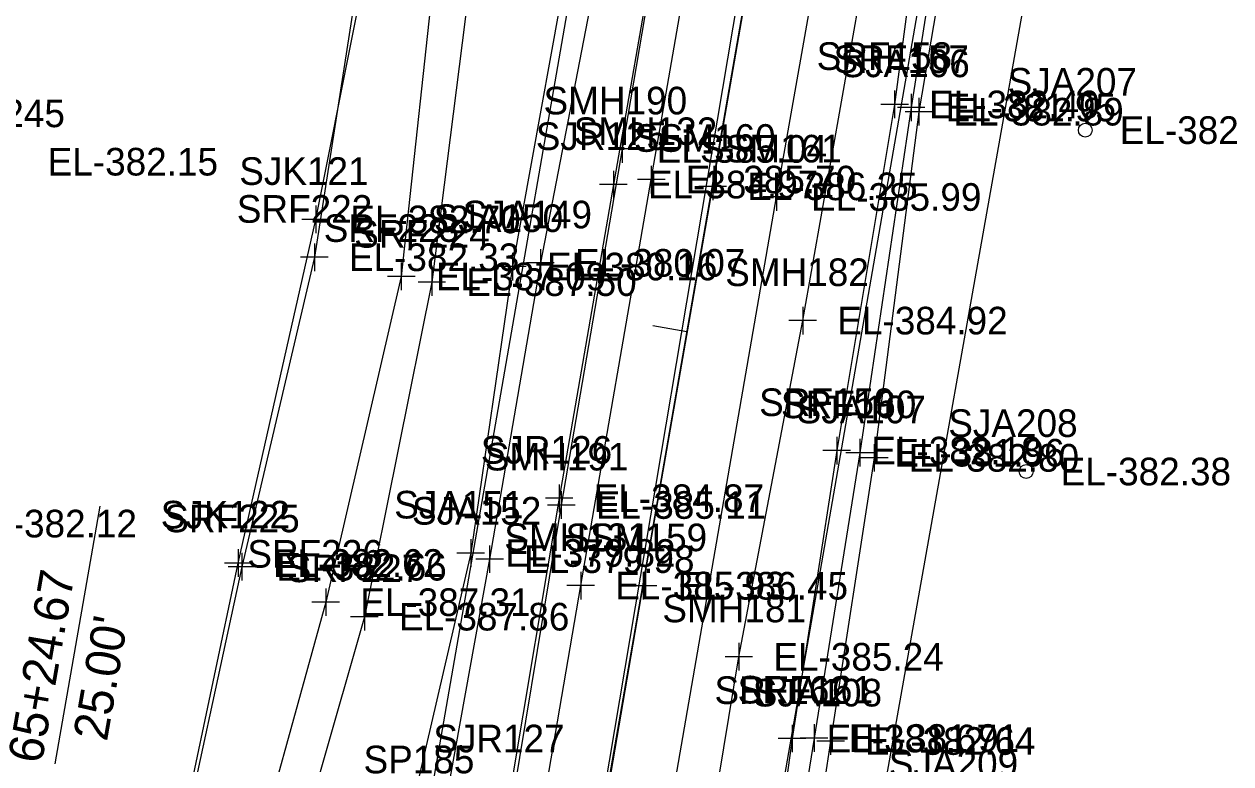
# Model space of a CAD drawing. Extents: x 1189978 to 1314812, y 571533 to 629339.
# Drawn here: x 1217588.4 to 1217763.2, y 622256.8 to 622363.9 of the extents above; entities that cross this region are included whole.
import ezdxf

# ---------------------------------------------------------------- set-up
doc = ezdxf.new("R2010")
doc.units = 0
for name, color, linetype in [('SURVEY - CENTERLINE - Preliminary', 7, 'Continuous'), ('SURVEY - CENTERLINE - Preliminary Text', 7, 'Continuous'), ('SURVEY - DRAINAGE - Area Shapes', 7, 'Continuous'), ('SURVEY - DTM - Breaklines', 7, 'Continuous'), ('SURVEY - DTM - Breaklines - Points - Elevations', 7, 'Continuous'), ('SURVEY - DTM - Breaklines - Points - Locators', 7, 'Continuous'), ('SURVEY - DTM - Breaklines - Points - Numbers', 7, 'Continuous'), ('SURVEY - DTM - Spot Points - Elevations', 7, 'Continuous'), ('SURVEY - DTM - Spot Points - Locators', 7, 'Continuous'), ('SURVEY - DTM - Spot Points - Point Numbers', 7, 'Continuous'), ('SURVEY - PROPERTY - ROW Lines', 7, 'Continuous'), ('SURVEY - PROPERTY - ROW Lines - Points - Numbers', 7, 'Continuous'), ('SURVEY - PROPERTY - Station and Offset Flags', 7, 'Continuous'), ('SURVEY - TRANSPORTATION - Roads', 7, 'Continuous'), ('SURVEY - TRANSPORTATION - Roads - Points - Elevations', 7, 'Continuous'), ('SURVEY - TRANSPORTATION - Roads - Points - Locators', 7, 'Continuous'), ('SURVEY - TRANSPORTATION - Roads - Points - Numbers', 7, 'Continuous'), ('SURVEY - UTILITIES - Electric (Overhead) with Text', 7, 'Continuous'), ('SURVEY - VEGETATION - Features - Points - Elevations', 7, 'Continuous'), ('SURVEY - VEGETATION - Features - Points - Locators', 7, 'Continuous'), ('SURVEY - VEGETATION - Features - Points - Numbers', 7, 'Continuous'), ('SURVEY - VEGETATION - Features with Text', 7, 'Continuous')]:
    doc.layers.add(name, color=color, linetype=linetype)

msp = doc.modelspace()

# ---------------------------------------------------------------- linework, layer by layer
at = {"layer": 'SURVEY - CENTERLINE - Preliminary'}
msp.add_line((1217671.49, 622245.09), (1217757.38, 622738.49), dxfattribs=at)
msp.add_line((1217671.49, 622245.09), (1217757.38, 622738.49), dxfattribs=at)
at = {"layer": 'SURVEY - CENTERLINE - Preliminary Text'}
msp.add_line((1217684.41, 622319.31), (1217679.48, 622320.17), dxfattribs=at)
at = {"layer": 'SURVEY - DRAINAGE - Area Shapes'}
msp.add_line((1217415.87, 620731.68), (1218149.36, 625079.9), dxfattribs=at)
at = {"layer": 'SURVEY - DTM - Breaklines'}
for points in [[(1217591.74, 621765.73), (1217601.34, 621822.74), (1217608.84, 621869.52), (1217625.54, 621971.19), (1217634.6, 622026.63), (1217643.17, 622076.74), (1217651.21, 622124.47), (1217659.56, 622173.57), (1217668.17, 622224.78), (1217678.08, 622282.54), (1217688.16, 622340.37), (1217697.26, 622392.62), (1217705.46, 622440.01), (1217714.49, 622490.86), (1217723.28, 622541.33), (1217731.44, 622588.51), (1217739.96, 622637.78), (1217748.52, 622688.04), (1217748.57, 622688.21), (1217756.95, 622738.51)], [(1217681.03, 622529.83), (1217673.16, 622499.61), (1217666.36, 622465.44), (1217655.82, 622419.52), (1217648.28, 622375.91), (1217643.04, 622327.33), (1217632.09, 622280.16), (1217619.71, 622235.27), (1217613.14, 622189.16), (1217602.51, 622145.75), (1217593.94, 622101.94), (1217587.9, 622057.35), (1217577.79, 622010.33), (1217570.45, 621965.56), (1217560.55, 621920.1), (1217546.67, 621868.08), (1217539.32, 621822.52), (1217534.84, 621801.11)], [(1217685.05, 622529.18), (1217678.55, 622499.44), (1217670.66, 622464.16), (1217662, 622418.29), (1217653.65, 622375.31), (1217647.46, 622326.5), (1217637.7, 622278.06), (1217624.97, 622233.51), (1217617.77, 622187.81), (1217609.29, 622147.05), (1217599.66, 622101.36), (1217592.56, 622056.45), (1217583.44, 622007.19), (1217575.28, 621964.22), (1217564.77, 621919.14), (1217554.54, 621865.01), (1217546.46, 621821.67), (1217537.02, 621781.08), (1217528.09, 621784.53), (1217517.71, 621784.08)], [(1217668.55, 622519.09), (1217665.88, 622505.91), (1217655.91, 622467.59), (1217646.62, 622422.12), (1217637.66, 622376.33), (1217630.45, 622330.1), (1217619.94, 622285.29), (1217610.06, 622239.5), (1217600.78, 622197.96), (1217592.86, 622149.6), (1217580.28, 622104.6), (1217573.51, 622060.94), (1217562.45, 622014.24), (1217553.23, 621969.79), (1217544.82, 621922.02), (1217535.21, 621868.88), (1217526.29, 621827.9)], [(1217696.43, 622511.42), (1217690.45, 622501.14), (1217682.75, 622461.47), (1217672.56, 622421.42), (1217668.77, 622381.8), (1217659.15, 622328.76), (1217653.09, 622287.28), (1217639.42, 622228.14), (1217631.31, 622175.39), (1217620.6, 622119.17), (1217610.69, 622074.17), (1217604.05, 622032.34), (1217595.02, 621981.54), (1217586.73, 621935.16), (1217578.82, 621892.7), (1217571.48, 621848.7), (1217561.74, 621801.1), (1217546.07, 621743.68), (1217517.89, 621741.61)], [(1217697.46, 622510.95), (1217695.23, 622500.63), (1217687.54, 622460.4), (1217680.36, 622419.79), (1217673.4, 622382.01), (1217663.19, 622329.29), (1217655.83, 622286.39), (1217645.17, 622227.36), (1217637.36, 622175.23), (1217627.75, 622118.91), (1217619.76, 622071.57), (1217612.88, 622029.47), (1217598.58, 621981.08), (1217592.58, 621934.99), (1217582.82, 621892.2), (1217576.26, 621849.18), (1217566.85, 621799.58), (1217549.42, 621742.26), (1217567.14, 621728.67)], [(1217704.42, 622509.33), (1217700.3, 622496.16), (1217691.81, 622446.34), (1217683.59, 622396.11), (1217675.05, 622345.79), (1217666.22, 622294.23), (1217657.54, 622241.9), (1217648.88, 622192.24), (1217640.73, 622142.53), (1217632.56, 622094.35), (1217625.38, 622048.54), (1217615.19, 621995.99), (1217607.27, 621946.79), (1217598.3, 621895.28), (1217589.38, 621843.86), (1217580.22, 621794.45), (1217573.72, 621781.31), (1217574.43, 621774.4), (1217580.6, 621768.52)], [(1217604.56, 621765.51), (1217608.59, 621775.31), (1217618.98, 621822.73), (1217628.13, 621872.31), (1217636.41, 621920.88), (1217646.75, 621970.08), (1217652.31, 622022.79), (1217663.53, 622069.73), (1217672.49, 622118.54), (1217678.26, 622168.97), (1217683.24, 622219.55), (1217691.94, 622272.25), (1217701.2, 622320.93), (1217709.61, 622368.48), (1217718.57, 622415.45), (1217724.25, 622459.08), (1217730.45, 622491.37), (1217730.86, 622507.08)], [(1217734.86, 622491.68), (1217727.91, 622445.78), (1217720.64, 622398.43), (1217714.5, 622352.23), (1217706.13, 622302.11), (1217699.65, 622260.42), (1217693, 622212.18), (1217687.82, 622174.51), (1217684.08, 622136.25), (1217675.85, 622096.46), (1217671.96, 622067.67), (1217669.46, 622048.53), (1217661.22, 621993.63), (1217653.56, 621948.52), (1217646.28, 621917), (1217643.83, 621906.18), (1217644.06, 621905.86), (1217641.41, 621873.35), (1217633.96, 621824.29), (1217625.6, 621785.71), (1217619.08, 621762.41), (1217607.58, 621724.78)], [(1217737.99, 622491.58), (1217731.67, 622445.99), (1217724.08, 622397.71), (1217716.9, 622351.79), (1217709.45, 622301.8), (1217702.84, 622260.49), (1217695.06, 622212.22), (1217690.49, 622174.72), (1217686.87, 622136.14), (1217680.45, 622095.18), (1217675.01, 622067.1), (1217678.26, 622054.48), (1217691.84, 622049.62), (1217699.98, 622049.72)], [(1217739.88, 622491.64), (1217732.77, 622445.6), (1217725.75, 622396.67), (1217718.01, 622351.18), (1217711.55, 622301.06), (1217705.23, 622260.06), (1217697.9, 622211.38), (1217691.93, 622173.62), (1217688.78, 622135.98), (1217683.07, 622094), (1217680.22, 622062.81), (1217683.31, 622059.64), (1217688.49, 622056.78), (1217698.9, 622055.52)]]:
    msp.add_lwpolyline(points, dxfattribs=at)
at = {"layer": 'SURVEY - DTM - Breaklines - Points - Locators'}
for p, q in [((1217714.5, 622354.23), (1217714.5, 622350.23)), ((1217716.9, 622353.79), (1217716.9, 622349.79)), ((1217718.01, 622353.18), (1217718.01, 622349.18)), ((1217716.5, 622352.23), (1217712.5, 622352.23)), ((1217718.9, 622351.79), (1217714.9, 622351.79)), ((1217720.01, 622351.18), (1217716.01, 622351.18)), ((1217675.05, 622347.79), (1217675.05, 622343.79)), ((1217677.05, 622345.79), (1217673.05, 622345.79)), ((1217688.16, 622342.37), (1217688.16, 622338.37)), ((1217690.16, 622340.37), (1217686.16, 622340.37)), ((1217630.45, 622332.1), (1217630.45, 622328.1)), ((1217659.15, 622330.76), (1217659.15, 622326.76)), ((1217663.19, 622331.29), (1217663.19, 622327.29)), ((1217632.45, 622330.1), (1217628.45, 622330.1)), ((1217643.04, 622329.33), (1217643.04, 622325.33)), ((1217661.15, 622328.76), (1217657.15, 622328.76)), ((1217665.19, 622329.29), (1217661.19, 622329.29)), ((1217645.04, 622327.33), (1217641.04, 622327.33)), ((1217647.46, 622328.5), (1217647.46, 622324.5)), ((1217649.46, 622326.5), (1217645.46, 622326.5)), ((1217701.2, 622322.93), (1217701.2, 622318.93)), ((1217703.2, 622320.93), (1217699.2, 622320.93)), ((1217706.13, 622304.11), (1217706.13, 622300.11)), ((1217709.45, 622303.8), (1217709.45, 622299.8)), ((1217711.55, 622303.06), (1217711.55, 622299.06)), ((1217708.13, 622302.11), (1217704.13, 622302.11)), ((1217711.45, 622301.8), (1217707.45, 622301.8)), ((1217713.55, 622301.06), (1217709.55, 622301.06)), ((1217666.22, 622296.23), (1217666.22, 622292.23)), ((1217668.22, 622294.23), (1217664.22, 622294.23)), ((1217653.09, 622289.28), (1217653.09, 622285.28)), ((1217619.94, 622287.29), (1217619.94, 622283.29)), ((1217655.09, 622287.28), (1217651.09, 622287.28)), ((1217655.83, 622288.39), (1217655.83, 622284.39)), ((1217621.94, 622285.29), (1217617.94, 622285.29)), ((1217657.83, 622286.39), (1217653.83, 622286.39)), ((1217678.08, 622284.54), (1217678.08, 622280.54)), ((1217632.09, 622282.16), (1217632.09, 622278.16)), ((1217680.08, 622282.54), (1217676.08, 622282.54)), ((1217634.09, 622280.16), (1217630.09, 622280.16)), ((1217637.7, 622280.06), (1217637.7, 622276.06)), ((1217639.7, 622278.06), (1217635.7, 622278.06)), ((1217691.94, 622274.25), (1217691.94, 622270.25)), ((1217693.94, 622272.25), (1217689.94, 622272.25)), ((1217699.65, 622262.42), (1217699.65, 622258.42)), ((1217702.84, 622262.49), (1217702.84, 622258.49)), ((1217704.84, 622260.49), (1217700.84, 622260.49)), ((1217705.23, 622262.06), (1217705.23, 622258.06)), ((1217701.65, 622260.42), (1217697.65, 622260.42)), ((1217707.23, 622260.06), (1217703.23, 622260.06))]:
    msp.add_line(p, q, dxfattribs=at)
at = {"layer": 'SURVEY - DTM - Spot Points - Locators'}
for centre in [(1217742.12, 622348.51), (1217733.56, 622299.08)]:
    msp.add_circle(centre, 1, dxfattribs=at)
at = {"layer": 'SURVEY - PROPERTY - ROW Lines'}
for p, q in [((1217646.86, 622249.38), (1217732.74, 622742.76)), ((1217696.12, 622240.81), (1217782.01, 622734.2))]:
    msp.add_line(p, q, dxfattribs=at)
at = {"layer": 'SURVEY - PROPERTY - Station and Offset Flags'}
msp.add_line((1217599.36, 622294.05), (1217592.87, 622256.75), dxfattribs=at)
at = {"layer": 'SURVEY - TRANSPORTATION - Roads'}
for points in [[(1217582.48, 621767.23), (1217583.27, 621767.61), (1217591.48, 621818.57), (1217599.69, 621870.76), (1217607.53, 621920.91), (1217615.95, 621971.91), (1217624.34, 622024.82), (1217633.57, 622076.49), (1217641.88, 622125.54), (1217650.64, 622175.68), (1217659.24, 622225.33), (1217669.03, 622282.56), (1217679.25, 622341.35), (1217687.87, 622391.11), (1217696.47, 622441.53), (1217705.33, 622491.37), (1217713.95, 622541.79), (1217722.13, 622587.98), (1217731.03, 622638.52), (1217739.75, 622690.1), (1217739.95, 622691.24)], [(1217602.44, 621764.03), (1217601.61, 621764.4), (1217609.73, 621817.52), (1217617.85, 621867.88), (1217626.38, 621920.56), (1217634.53, 621969.83), (1217643.58, 622024.64), (1217652.44, 622075.54), (1217660.7, 622123.44), (1217668.82, 622172.59), (1217677.49, 622224.09), (1217697.4, 622338.83), (1217706.31, 622389.43), (1217714.67, 622438.11), (1217723.73, 622488.94), (1217732.47, 622539.47), (1217740.61, 622586), (1217749.34, 622636.23), (1217757.51, 622686.56)]]:
    msp.add_lwpolyline(points, dxfattribs=at)
at = {"layer": 'SURVEY - TRANSPORTATION - Roads - Points - Locators'}
for p, q in [((1217679.25, 622343.35), (1217679.25, 622339.35)), ((1217681.25, 622341.35), (1217677.25, 622341.35)), ((1217697.4, 622340.83), (1217697.4, 622336.83)), ((1217699.4, 622338.83), (1217695.4, 622338.83)), ((1217669.03, 622284.56), (1217669.03, 622280.56)), ((1217671.03, 622282.56), (1217667.03, 622282.56))]:
    msp.add_line(p, q, dxfattribs=at)
at = {"layer": 'SURVEY - UTILITIES - Electric (Overhead) with Text'}
msp.add_lwpolyline([(1217806.14, 622777), (1217743.09, 622422.64), (1217688.2, 622113.29), (1217626.83, 621775.19), (1217569.14, 621442.23), (1217508.83, 621100.02), (1217448.24, 620751.9)], dxfattribs=at)
at = {"layer": 'SURVEY - VEGETATION - Features - Points - Locators'}
for p, q in [((1217673.76, 622342.63), (1217673.76, 622338.63)), ((1217675.76, 622340.63), (1217671.76, 622340.63)), ((1217630.65, 622337.58), (1217630.65, 622333.58)), ((1217632.65, 622335.58), (1217628.65, 622335.58)), ((1217665.91, 622297.21), (1217665.91, 622293.21)), ((1217667.91, 622295.21), (1217663.91, 622295.21)), ((1217619.43, 622287.83), (1217619.43, 622283.83)), ((1217621.43, 622285.83), (1217617.43, 622285.83))]:
    msp.add_line(p, q, dxfattribs=at)
at = {"layer": 'SURVEY - VEGETATION - Features with Text'}
for points in [[(1217575.08, 621774.11), (1217450.26, 621814.85), (1217450.11, 621824.86), (1217507.38, 621858.46), (1217523.69, 621881.47), (1217539.67, 621940.19), (1217555.11, 622005.06), (1217569.39, 622072.91), (1217588.39, 622140.3), (1217598.23, 622184.22), (1217608.56, 622234.27), (1217619.43, 622285.83), (1217630.65, 622335.58), (1217641.81, 622391.46), (1217652.67, 622449.04), (1217659.71, 622500.99), (1217665.15, 622519.94)], [(1217702.96, 622509.49), (1217699.51, 622493.95), (1217693.48, 622453.44), (1217687.22, 622414.99), (1217679.9, 622375.82), (1217673.76, 622340.63), (1217665.91, 622295.21), (1217658.91, 622253.42), (1217654.9, 622206.36), (1217645.64, 622163.87), (1217637.41, 622119.23), (1217630.2, 622079.47), (1217625.49, 622037.7), (1217617.96, 622003.15), (1217610.75, 621959.64), (1217601.11, 621912.04), (1217596.35, 621872.4), (1217583.12, 621827.95), (1217575.08, 621774.11)]]:
    msp.add_lwpolyline(points, dxfattribs=at)

# ---------------------------------------------------------------- texts
at = {"layer": 'SURVEY - DTM - Breaklines - Points - Elevations'}
for s, p in [('EL-382.40', (1217719.5, 622350.23)), ('EL-381.95', (1217721.9, 622349.79)), ('EL-382.89', (1217723.01, 622349.18)), ('EL-385.04', (1217680.05, 622343.79)), ('EL-386.25', (1217693.16, 622338.37)), ('EL-382.33', (1217635.45, 622328.1)), ('EL-380.16', (1217664.15, 622326.76)), ('EL-380.07', (1217668.19, 622327.29)), ('EL-387.09', (1217648.04, 622325.33)), ('EL-387.50', (1217652.46, 622324.5)), ('EL-384.92', (1217706.2, 622318.93)), ('EL-382.18', (1217711.13, 622300.11)), ('EL-381.96', (1217714.45, 622299.8)), ('EL-382.80', (1217716.55, 622299.06)), ('EL-385.11', (1217671.22, 622292.23)), ('EL-379.82', (1217658.09, 622285.28)), ('EL-379.98', (1217660.83, 622284.39)), ('EL-382.66', (1217624.94, 622283.29)), ('EL-386.45', (1217683.08, 622280.54)), ('EL-387.31', (1217637.09, 622278.16)), ('EL-387.86', (1217642.7, 622276.06)), ('EL-385.24', (1217696.94, 622270.25)), ('EL-381.67', (1217704.65, 622258.42)), ('EL-381.91', (1217707.84, 622258.49)), ('EL-382.64', (1217710.23, 622258.06))]:
    msp.add_text(s, height=4, dxfattribs=at).set_placement(p)
at = {"layer": 'SURVEY - DTM - Breaklines - Points - Numbers'}
for s, p in [('SRF158', (1217703.21, 622357.23)), ('SRF157', (1217705.66, 622356.79)), ('SJA106', (1217706.66, 622356.18)), ('SMH190', (1217663.64, 622350.79)), ('SSM160', (1217676.75, 622345.37)), ('SRF222', (1217619.21, 622335.1)), ('SJA150', (1217647.74, 622333.76)), ('SJA149', (1217651.93, 622334.29)), ('SRF223', (1217631.8, 622332.33)), ('SRF224', (1217636.22, 622331.5)), ('SMH182', (1217689.96, 622325.93)), ('SRF159', (1217694.88, 622307.11)), ('SRF160', (1217698.03, 622306.8)), ('SJA107', (1217700.31, 622306.06)), ('SMH191', (1217655.14, 622299.23)), ('SJA151', (1217642.01, 622292.28)), ('SJA152', (1217644.59, 622291.39)), ('SRF225', (1217608.7, 622290.29)), ('SSM159', (1217666.83, 622287.54)), ('SRF226', (1217620.74, 622285.16)), ('SRF227', (1217626.46, 622283.06)), ('SMH181', (1217680.86, 622277.25)), ('SRF162', (1217688.41, 622265.42)), ('SRF161', (1217691.75, 622265.49)), ('SJA108', (1217693.95, 622265.06))]:
    msp.add_text(s, height=4, dxfattribs=at).set_placement(p)
at = {"layer": 'SURVEY - DTM - Spot Points - Elevations'}
for s, p in [('EL-382.60', (1217747.12, 622346.51)), ('EL-382.15', (1217591.81, 622341.94)), ('EL-382.38', (1217738.56, 622297.08)), ('EL-382.12', (1217580.06, 622289.54))]:
    msp.add_text(s, height=4, dxfattribs=at).set_placement(p)
at = {"layer": 'SURVEY - DTM - Spot Points - Point Numbers'}
for s, p in [('SJA207', (1217730.88, 622353.51)), ('SJA245', (1217575.57, 622348.94)), ('SJA208', (1217722.28, 622304.08)), ('SJA209', (1217713.67, 622254.79))]:
    msp.add_text(s, height=4, dxfattribs=at).set_placement(p)
at = {"layer": 'SURVEY - PROPERTY - ROW Lines - Points - Numbers'}
msp.add_text('SP185', height=4, dxfattribs=at).set_placement((1217637.57, 622255.38))
at = {"layer": 'SURVEY - PROPERTY - Station and Offset Flags'}
for s, p in [('65+24.67', (1217590.94, 622256.65)), ("25.00'", (1217600.39, 622259.88))]:
    msp.add_text(s, height=5, rotation=80.1256, dxfattribs=at).set_placement(p)
at = {"layer": 'SURVEY - TRANSPORTATION - Roads - Points - Elevations'}
for s, p in [('EL-385.70', (1217684.25, 622339.35)), ('EL-385.99', (1217702.4, 622336.83)), ('EL-385.93', (1217674.03, 622280.56))]:
    msp.add_text(s, height=4, dxfattribs=at).set_placement(p)
at = {"layer": 'SURVEY - TRANSPORTATION - Roads - Points - Numbers'}
for s, p in [('SMH132', (1217668.01, 622346.35)), ('SSM161', (1217686.32, 622343.83)), ('SMH131', (1217657.95, 622287.56))]:
    msp.add_text(s, height=4, dxfattribs=at).set_placement(p)
at = {"layer": 'SURVEY - VEGETATION - Features - Points - Elevations'}
for s, p in [('EL-384.97', (1217678.76, 622338.63)), ('EL-382.70', (1217635.65, 622333.58)), ('EL-384.87', (1217670.91, 622293.21)), ('EL-382.62', (1217624.43, 622283.83))]:
    msp.add_text(s, height=4, dxfattribs=at).set_placement(p)
at = {"layer": 'SURVEY - VEGETATION - Features - Points - Numbers'}
for s, p in [('SJR125', (1217662.52, 622345.63)), ('SJK121', (1217619.57, 622340.58)), ('SJR126', (1217654.56, 622300.21)), ('SJK122', (1217608.19, 622290.83)), ('SJR127', (1217647.67, 622258.42))]:
    msp.add_text(s, height=4, dxfattribs=at).set_placement(p)

doc.saveas('drawing.dxf')
